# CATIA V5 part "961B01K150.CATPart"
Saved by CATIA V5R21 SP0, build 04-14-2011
Part number: 961B01K150
Bounding box of the stored display mesh (mm): x -18.1 to 18.1, y -75 to 75, z -10 to 4.5
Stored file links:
  C:\Users\ALI OZGUN\Desktop\alhan\961B01K150.CATPart
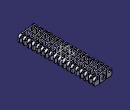
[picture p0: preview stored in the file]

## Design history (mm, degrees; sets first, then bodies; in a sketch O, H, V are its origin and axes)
Body1 (main body)
  Sketch1 on zx-plane, origin (0, 0, 0), H (-1, 0, 0), V (0, 0, 1)
    construction line L1 (-13.6, 0) -> (13.6, 0)
    point P1 (-13.6, 0)
    line L2 (-13.6, 4.5) -> (13.6, 4.5)
    line L3 (13.6, -4.5) -> (-13.6, -4.5)
    arc A1 centre (13.6, 0) radius 4.5 from (13.6, 4.5) to (13.6, -4.5) cw
    arc A2 centre (-13.6, 0) radius 4.5 from (-13.6, -4.5) to (-13.6, 4.5) cw
    distance L1 L2 = 4.5
    length L1 = 27.2
    distance P1 V = 13.6
    coincidence: P1 H
    horizontal: L1 H
    tangency: A1 L2, A2 L2, A1 L3, A2 L3
  Sketch2 on zx-plane, origin (0, 0, 0), H (-1, 0, 0), V (0, 0, 1)
    point P1 (-2.5, -4.5)
    line L1 (-2.5, -4.5) -> (-0.4806, 2.5379)
    point P2 (0, 4.2129)
    line L2 (0.4806, 2.5379) -> (2.5, -4.5)
    point P3 (2.5, -4.5)
    line L3 (2.5, -4.5) -> (-2.5, -4.5)
    arc A1 centre (0, 2.4) radius 0.5 from (-0.4806, 2.5379) to (0.4806, 2.5379) cw
    distance P3 P1 = 5
    distance L3 H = 4.5
    radius A1 = 0.5
    distance A1 L3 = 7.4
    horizontal: L3 H
    coincidence: L1 P2, L2 P2
    tangency: A1 L1, A1 L2
    symmetry: L1 L2 V
  Pad1: profile Sketch2, direction (0, 1, 0), length 25, mirrored extent
  Body2
    Pad2: profile Sketch6, direction (0, 0, 1), length 25, mirrored extent
    Pocket1: profile Sketch1, direction (0, -1, 0), length 25, outer side
    Fillet1: radius 5, on edge [face of Pad2 from Sketch6.L3 | face of Pad2 from Sketch6.L2]; edge [face of Pad2 from Sketch6.L8 | face of Pad2 from Sketch6.L7]; edge [face of Pad2 from Sketch6.L7 | face of Pad2 from Sketch6.L4]; edge [face of Pad2 from Sketch6.L2 | face of Pad2 from Sketch6.L1]
    RectPattern1: of the body so far, direction 1 instances 6, spacing 8.52, along yz-plane
    Sketch3 on face of Pad2 from Sketch6.L1, origin (0, -23.3, 0), H (1, 0, 0), V (0, 0, 1)
      arc A1 centre (-13.6, 0) radius 4.5 from (-9.1, 0) to (-18.1, 0) ccw
      line L1 (-9.2, 0) -> (-11.15, 0)
      arc A2 centre (-13.6, 0) radius 2.45 from (-11.15, 0) to (-16.05, 0) ccw
      reference projected arc E1 centre (-13.6, 0) radius 4.5 from (-13.6, 4.5) to (-13.6, -4.5) ccw from edge [face of Pocket1 from Sketch1.A1 | face of Pad2 from Sketch6.L1]
      point P5 (-16.05, 0)
      line L2 (-16.05, 0) -> (-18.1, 0)
      radius A1 = 4.5
      radius A2 = 2.45
      horizontal: L1 H, L2 H
      coincidence: L1 H, L1 P5, L1 L2
      concentricity: A1 E1
    Pad3: profile Sketch3, direction (0, -1, 0), length 1.7
    RectPattern2: of Pad3, direction 1 instances 6, spacing 8.52, along axis of face of Pocket1 from Sketch1.A2
    Sketch4 on face of RectPattern1, origin (0, 23.3, 0), H (-1, 0, 0), V (0, 0, 1)
      arc A1 centre (-13.6, 0) radius 4.5 from (-18.1, 0) to (-9.1, 0) cw
      line L1 (-18.1, 0) -> (-16.05, 0)
      arc A2 centre (-13.6, 0) radius 2.45 from (-16.05, 0) to (-11.15, 0) cw
      line L2 (-11.15, 0) -> (-9.1, 0)
      reference projected arc E1 centre (-13.6, 0) radius 4.5 from (-13.6, 4.5) to (-13.6, -4.5) ccw from edge [face of RectPattern1 | face of RectPattern1]
      reference projected line E2 (-7.6525, 4.5) -> (-13.6, 4.5) from edge [face of RectPattern1 | face of RectPattern1]
      radius A2 = 2.45
      distance L2 H = 0
      concentricity: A1 E1, A2 A1
      coincidence: L1 L2
      tangency: A1 E2
    Pad4: profile Sketch4, direction (0, 1, 0), length 1.7, opposite side length 1
    RectPattern3: of Pad4, direction 1 instances 6, spacing 8.52, along axis of face of RectPattern1 reversed
    Sketch5 on zx-plane, origin (0, 0, 0), H (-1, 0, 0), V (0, 0, 1)
      circle A1 centre (-13.6, 0) radius 2.45
      point P1 (-13.6, 0)
      circle A2 centre (13.6, 0) radius 2.4
      point P2 (13.6, 0)
      reference projected arc E1 centre (-13.6, 0) radius 2.45 from (-11.15, 0) to (-16.05, 0) ccw from edge [face of Pad4 from Sketch4.A2 | end face of Pad4]
      reference projected arc E2 centre (13.6, 0) radius 4.5 from (13.6, -4.5) to (13.6, 4.5) ccw from edge [face of RectPattern1 | face of RectPattern2]
      radius A2 = 2.4
      radius A1 = 2.45
      coincidence: P1 H, P2 H
      concentricity: A1 E1, A2 E2
    Pocket2: profile Sketch5, direction (0, -1, 0), length 32.7, mirrored extent
  Add1: tool Body2
  Body3
    Solid1: solid without history
  Add2: tool Body3
  Body4
    Solid2: solid without history
    Translate1: Direction zx-plane, Length -100, ToTransfor Solid2
  Add3: tool Body4
  Body5
    Solid3: solid without history
    Translate2: Direction zx-plane, ToTransfor Solid3, Length 50
  Add4: tool Body5
  Body6
    Solid4: solid without history
  Add5: tool Body6
  Body7
    Solid5: solid without history
    Translate3: Direction zx-plane, ToTransfor Solid5, Length -50
  Add6: tool Body7
  Sketch6 on xy-plane, origin (0, 0, 0), H (1, 0, 0), V (0, 1, 0)
    line L1 (-19.0192, -23.3) -> (-7.5, -23.3)
    point P1 (-7.5, -23.3)
    line L2 (-7.5, -23.3) -> (7.5, -21.6)
    point P2 (7.5, -21.6)
    line L3 (7.5, -21.6) -> (20, -21.6)
    point P3 (20, -21.6)
    line L4 (7.3701, -19.3) -> (20, -19.3)
    point P4 (7.5, -19.3)
    construction line L5 (7.5, -21.6) -> (7.5, -19.3)
    construction line L6 (20, -21.6) -> (20, -19.3)
    line L7 (-7.759, -21.0146) -> (7.3701, -19.3)
    point P6 (-7.759, -21.0146)
    line L8 (-19.0192, -21.0146) -> (-7.759, -21.0146)
    line L9 (20, -19.3) -> (20, -21.6)
    line L10 (-19.0192, -21.0146) -> (-19.0192, -23.3)
    reference projected line E2 (-2.5, -25) -> (-0.4806, -25) from edge [start face of Pad1 | face of Pad1 from Sketch2.L2]
    distance P1 P2 H = 15
    distance L1 L3 = 1.7
    distance P1 V = 7.5
    distance P2 P3 = 12.5
    distance L3 L4 = 2.3
    distance L1 E2 = 1.7
    distance L10 L9 = 39.0192
    distance L8 L1 = 2.2854
    distance L7 L2 = 2.3
    horizontal: L1 H, L3 H
    perpendicularity: L5 L3, L5 L4, L6 L3, L6 L4
    coincidence: L8 P6, P4 L4, P6 L7
    vertical: L9 V, L10 V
